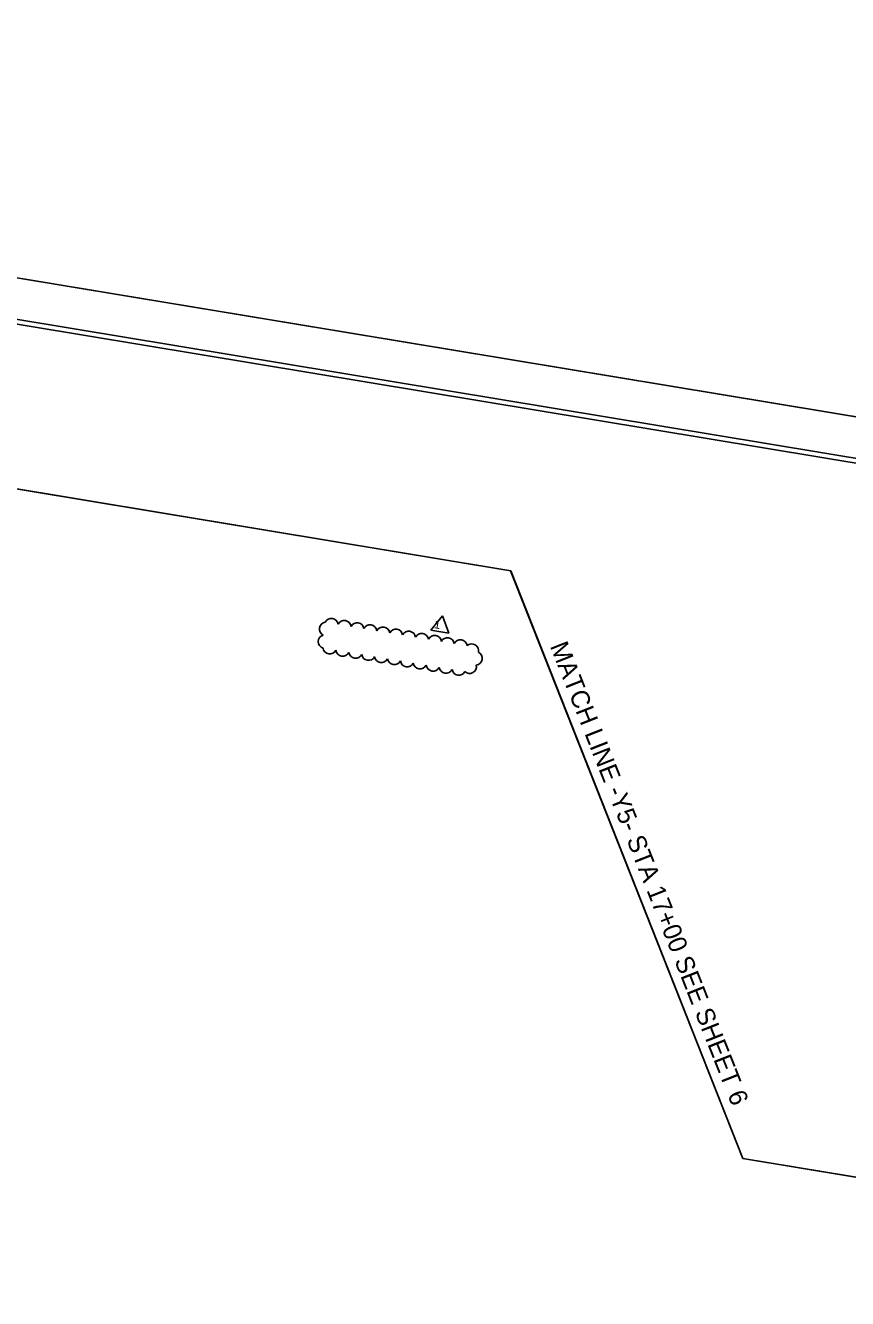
# Model space of a CAD drawing. Extents: x 2191153 to 2193185, y 85349 to 86740.
# Drawn here: x 2192169 to 2192618, y 86044 to 86740 of the extents above; entities that cross this region are included whole.
import ezdxf

# ---------------------------------------------------------------- set-up
doc = ezdxf.new("R2010")
doc.units = 0
for name, color, linetype in [('CTL Primary Horizontal Cogo Comment', 7, 'Continuous'), ('CTL Primary Horizontal Cogo Elevation', 7, 'Continuous'), ('CTL Primary Horizontal Cogo Number', 7, 'Continuous'), ('Exist Other Culture Sign', 7, 'Continuous'), ('Exist Property Iron Pin Cogo Number', 7, 'Continuous'), ('Exist Utilities Other Traffic Signal Box CELL', 7, 'Continuous'), ('Old_Level_6', 7, 'Continuous')]:
    doc.layers.add(name, color=color, linetype=linetype)

msp = doc.modelspace()

# ---------------------------------------------------------------- linework, layer by layer
at = {"layer": 'CTL Primary Horizontal Cogo Comment'}
msp.add_line((2192993.8, 86464.39), (2191332.46, 86739.67), dxfattribs=at)
at = {"layer": 'CTL Primary Horizontal Cogo Elevation'}
msp.add_lwpolyline([(2192993.8, 86464.39), (2191332.46, 86739.67), (2191152.64, 85654.47), (2192813.99, 85379.19)], close=True, dxfattribs=at)
at = {"layer": 'CTL Primary Horizontal Cogo Number'}
msp.add_lwpolyline([(2192985.69, 86442.98), (2191341.61, 86715.4), (2191169.13, 85674.49), (2192813.22, 85402.07)], close=True, dxfattribs=at)
at = {"layer": 'Exist Other Culture Sign'}
msp.add_lwpolyline([(2192972.95, 86442.51), (2191493.12, 86687.71), (2191321.48, 85651.84), (2192801.3, 85406.63)], close=True, dxfattribs=at)
at = {"layer": 'Exist Property Iron Pin Cogo Number'}
for p, q in [((2192433.98, 86441.81), (2191478.61, 86600.12)), ((2192560.65, 86120.88), (2192433.79, 86441.74)), ((2192560.71, 86120.87), (2192910.06, 86062.98))]:
    msp.add_line(p, q, dxfattribs=at)
at = {"layer": 'Exist Utilities Other Traffic Signal Box CELL'}
msp.add_lwpolyline([(2192560.71, 86120.87), (2192910.06, 86062.98), (2192813.63, 85481.03), (2192809.37, 85455.33), (2192553.73, 85497.72), (2192545.63, 85449), (2191321.48, 85651.84), (2191478.61, 86600.12), (2192433.98, 86441.81)], close=True, dxfattribs=at)
at = {"layer": 'Old_Level_6'}
for p, q in [((2192390.39, 86409.36), (2192396.73, 86417.23)), ((2192396.73, 86417.23), (2192400.19, 86407.74)), ((2192390.39, 86409.36), (2192400.19, 86407.74))]:
    msp.add_line(p, q, dxfattribs=at)
for centre, radius, start, end in [((2192333.2, 86410.05), 3.74, 98.09168, 243.09168), ((2192336.01, 86412.06), 3.74, 8.09168, 153.09168), ((2192343.06, 86410.89), 3.74, 8.09168, 153.09168), ((2192350.1, 86409.73), 3.74, 8.09168, 153.09168), ((2192332.61, 86403.13), 3.74, 107.09878, 252.09878), ((2192357.14, 86408.56), 3.74, 8.09168, 153.09168), ((2192364.19, 86407.39), 3.74, 8.09168, 153.09168), ((2192371.23, 86406.22), 3.74, 8.09168, 153.09168), ((2192378.28, 86405.06), 3.74, 8.09168, 153.09168), ((2192385.32, 86403.89), 3.74, 8.09168, 153.09168), ((2192392.36, 86402.72), 3.74, 8.09168, 153.09168), ((2192335.16, 86400.1), 3.74, 188.09168, 333.09168), ((2192399.41, 86401.56), 3.74, 8.09168, 153.09168), ((2192406.45, 86400.39), 3.74, 8.09168, 153.09168), ((2192412.66, 86398.13), 3.75, 347.03706, 132.03706), ((2192342.21, 86398.93), 3.74, 188.09168, 333.09168), ((2192349.25, 86397.77), 3.74, 188.09168, 333.09168), ((2192356.3, 86396.6), 3.74, 188.09168, 333.09168), ((2192363.34, 86395.43), 3.74, 188.09168, 333.09168), ((2192370.38, 86394.26), 3.74, 188.09168, 333.09168), ((2192377.43, 86393.1), 3.74, 188.09168, 333.09168), ((2192414.62, 86393.96), 3.74, 278.09168, 63.09168), ((2192384.47, 86391.93), 3.74, 188.09168, 333.09168), ((2192391.51, 86390.76), 3.74, 188.09168, 333.09168), ((2192398.56, 86389.6), 3.74, 188.09168, 333.09168), ((2192405.6, 86388.43), 3.74, 188.09168, 333.09168), ((2192411.49, 86389.47), 3.74, 227.0325, 12.0325)]:
    msp.add_arc(centre, radius, start, end, dxfattribs=at)

# ---------------------------------------------------------------- texts
at = {"layer": 'Exist Property Iron Pin Cogo Number'}
msp.add_text('MATCH LINE -Y5- STA 17+00 SEE SHEET 6', height=10, rotation=291.58018, dxfattribs=at).set_placement((2192455.22, 86400.73))
at = {"layer": 'Old_Level_6'}
msp.add_text(' 1', height=4.5, rotation=350.59168, dxfattribs=at).set_placement((2192390.23, 86410.79))

doc.saveas('drawing.dxf')
